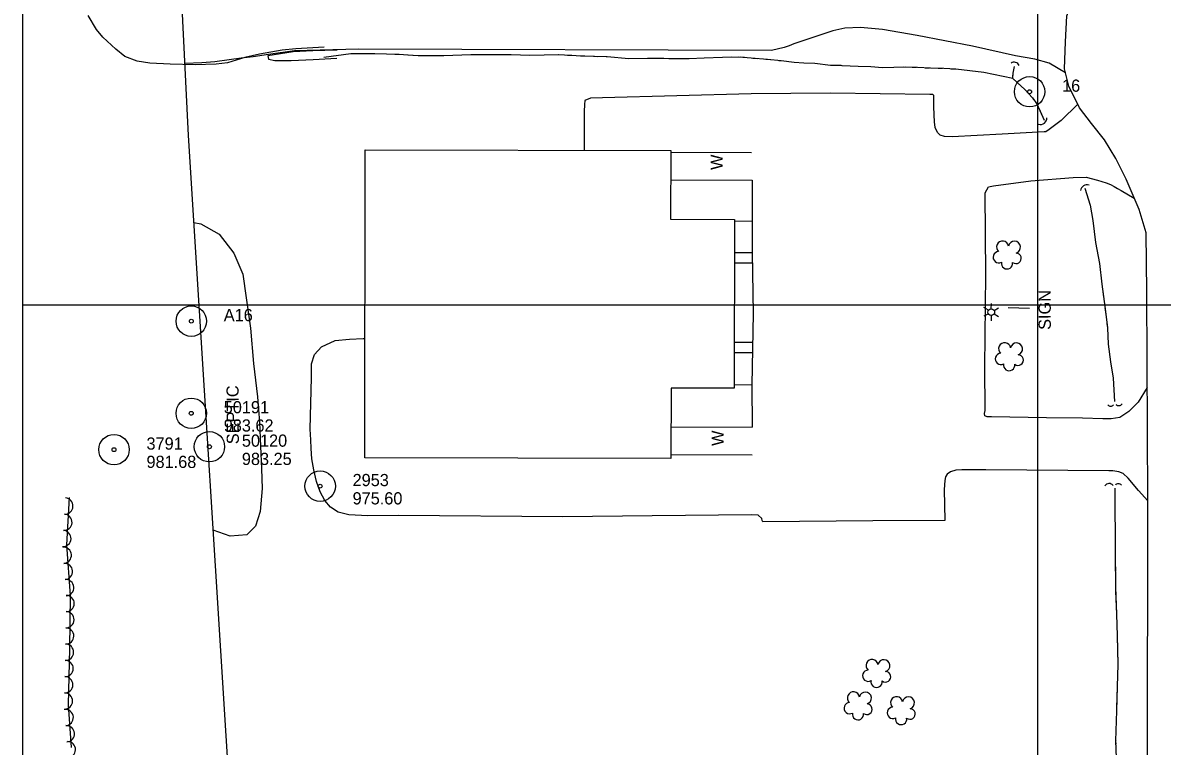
# Model space of a CAD drawing. Extents: x 353423 to 364002, y 127000 to 201942.
# Drawn here: x 360000 to 360561, y 134283 to 134639 of the extents above; entities that cross this region are included whole.
import ezdxf

# ---------------------------------------------------------------- set-up
doc = ezdxf.new("R2010")
doc.units = 0
for name, color, linetype in [('E_DTM_SlopeBottom', 7, 'Continuous'), ('E_DTM_SlopeTop', 7, 'Continuous'), ('E_FEN_Generic', 7, 'Continuous'), ('E_LAND_BrushLine', 7, 'Continuous'), ('E_LAND_TreeLine', 7, 'Continuous'), ('E_MISCPROP', 7, 'Continuous'), ('E_RDWY_AsphConc', 7, 'Continuous'), ('E_RDWY_Gravel', 7, 'Continuous'), ('E_STRUCT_WingWall', 7, 'Continuous'), ('E_UTL_ETransformer', 7, 'Continuous'), ('E_WTR_FlowLine', 7, 'Continuous')]:
    doc.layers.add(name, color=color, linetype=linetype)

msp = doc.modelspace()

# ---------------------------------------------------------------- linework, layer by layer
at = {"layer": 'E_DTM_SlopeBottom'}
for points in [[(360319.17, 134575.09), (360358.92, 134574.91)], [(360319.15, 134561.46), (360359.28, 134561.35)], [(360319.27, 134439.83), (360359.23, 134439.78)], [(360319.25, 134426.18), (360359.19, 134426.11)]]:
    msp.add_lwpolyline(points, dxfattribs=at)
for centre, radius, start, end in [((360488.37, 134616.83), 2.57, 22.214, 128.4535), ((360501.19, 134591.99), 3.26, 254.8922, 1.1318), ((360524.12, 134555.93), 3.07, 69.1026, 175.3422), ((360539.85, 134452.26), 1.96, 222.417, 328.6565), ((360535.83, 134451.76), 1.72, 217.3993, 323.6389), ((360535.08, 134409.43), 2.52, 38.8099, 145.0494), ((360539.67, 134410.02), 1.86, 38.2653, 144.5049)]:
    msp.add_arc(centre, radius, start, end, dxfattribs=at)
at = {"layer": 'E_DTM_SlopeTop'}
msp.add_lwpolyline([(360554.05, 134269.46), (360554.09, 134403.92), (360553.63, 134506.29), (360553.37, 134535.42), (360549.86, 134546.8), (360543.54, 134561.85), (360538.34, 134571.93), (360532.81, 134581.11), (360526.34, 134589.2), (360520.57, 134596.9), (360515.23, 134607.66), (360513.1, 134616.09), (360513.61, 134629.43), (360514.27, 134642.21), (360517.01, 134649.05), (360520.34, 134654.93), (360525, 134659.58), (360529.55, 134664.15), (360535.92, 134669.8), (360542.83, 134674.49), (360548.9, 134677.17), (360554.53, 134678.74), (360561.11, 134679.89), (360568.24, 134680.29)], dxfattribs=at)
at = {"layer": 'E_FEN_Generic'}
msp.add_lwpolyline([(360024.07, 134281.98), (360022.56, 134302.95), (360023.16, 134330.76), (360023.5, 134356.82), (360021.67, 134381.8), (360023.09, 134405.02)], dxfattribs=at)
for centre, radius, start, end in [((360482.6, 134528.4), 2.97, 8.4104, 229.6443), ((360488.45, 134528.29), 2.97, 286.0613, 169.0345), ((360480.74, 134523.36), 2.78, 91.3813, 299.1543), ((360489.22, 134522.82), 2.61, 230.7665, 88.6991), ((360484.82, 134520.36), 2.78, 168.0584, 9.0694), ((360483.63, 134478.32), 2.97, 8.4104, 229.6443), ((360489.48, 134478.21), 2.97, 286.0613, 169.0345), ((360481.77, 134473.28), 2.78, 91.3813, 299.1543), ((360490.24, 134472.74), 2.61, 230.7665, 88.6991), ((360485.84, 134470.28), 2.78, 168.0584, 9.0694), ((360020.74, 134400.88), 4, 266.5093, 86.4939), ((360020.25, 134392.89), 4, 266.5093, 86.4939), ((360019.76, 134384.91), 4, 266.5093, 86.4939), ((360019.95, 134376.65), 4, 274.2019, 94.1866), ((360020.53, 134368.67), 4, 274.2019, 94.1866), ((360021.12, 134360.69), 4, 274.2019, 94.1866), ((360021.36, 134352.89), 4, 269.2523, 89.237), ((360021.25, 134344.89), 4, 269.2523, 89.237), ((360021.15, 134336.89), 4, 269.2523, 89.237), ((360021.03, 134328.91), 4, 268.771, 88.7557), ((360020.85, 134320.91), 4, 268.771, 88.7557), ((360418.31, 134322.38), 2.97, 8.4104, 229.6443), ((360424.17, 134322.27), 2.97, 286.0613, 169.0345), ((360020.68, 134312.92), 4, 268.771, 88.7557), ((360416.45, 134317.34), 2.78, 91.3813, 299.1543), ((360424.93, 134316.8), 2.61, 230.7665, 88.6991), ((360420.53, 134314.34), 2.78, 168.0584, 9.0694), ((360020.51, 134304.92), 4, 268.771, 88.7557), ((360409.16, 134306.42), 2.97, 8.4104, 229.6443), ((360415.02, 134306.31), 2.97, 286.0613, 169.0345), ((360430.4, 134304.07), 2.97, 8.4104, 229.6443), ((360436.25, 134303.96), 2.97, 286.0613, 169.0345), ((360020.91, 134296.74), 4, 274.1321, 94.1168), ((360407.3, 134301.38), 2.78, 91.3813, 299.1543), ((360415.78, 134300.84), 2.61, 230.7665, 88.6991), ((360428.54, 134299.03), 2.78, 91.3813, 299.1543), ((360437.02, 134298.49), 2.61, 230.7665, 88.6991), ((360411.38, 134298.38), 2.78, 168.0584, 9.0694), ((360432.62, 134296.03), 2.78, 168.0584, 9.0694), ((360021.48, 134288.76), 4, 274.1321, 94.1168), ((360021.96, 134280.97), 4, 268.8197, 88.8044)]:
    msp.add_arc(centre, radius, start, end, dxfattribs=at)
at = {"layer": 'E_LAND_BrushLine'}
for p, q in [((360475.61, 134497.27), (360473.37, 134498.62)), ((360477.05, 134498.01), (360477.11, 134500.53)), ((360478.51, 134497.14), (360480.67, 134498.39)), ((360495.9, 134498.11), (360485.41, 134498.4)), ((360475.61, 134495.56), (360473.32, 134494.35)), ((360476.98, 134494.74), (360476.92, 134492.13)), ((360478.47, 134495.5), (360480.67, 134494.15))]:
    msp.add_line(p, q, dxfattribs=at)
msp.add_circle((360477.04, 134496.37), 1.64, dxfattribs=at)
at = {"layer": 'E_LAND_TreeLine'}
for p, q in [((360000, 134500), (360000, 136500)), ((360500, 134500), (360500, 136500)), ((360000, 132500), (360000, 135000)), ((360500, 132500), (360500, 135000)), ((360000, 134500), (364000, 134500)), ((360000, 134500), (364000, 134500))]:
    msp.add_line(p, q, dxfattribs=at)
at = {"layer": 'E_MISCPROP'}
for points in [[(360148.41, 134626.81), (360134.44, 134625.99), (360127.68, 134625.25), (360116.54, 134623.26), (360109.34, 134621.65), (360100.86, 134619.07), (360095.17, 134618.39), (360084.94, 134618.13), (360072.65, 134618.35), (360062.64, 134618.9), (360056.3, 134619.84), (360050.22, 134622.25), (360045.88, 134625.81), (360039.35, 134631.73), (360036.36, 134635.51), (360032.27, 134642.31)], [(360513.58, 134614.18), (360505.53, 134618.94), (360498.48, 134620.86), (360488.94, 134622.5), (360467.79, 134627.31), (360440.5, 134632.46), (360423.4, 134635.46), (360412.7, 134636.52), (360404.92, 134636.15), (360398.94, 134634.85), (360387.69, 134631.08), (360379.87, 134628.39), (360377.51, 134627.37), (360374.95, 134626.6), (360368.85, 134625.21), (360165.32, 134625.86), (360133.82, 134625.03), (360121.02, 134623.14), (360113.42, 134622.07), (360107.54, 134621.36), (360101.62, 134620.53), (360094.63, 134619.51), (360088.13, 134619.06), (360079.88, 134618.7)], [(360154.87, 134625.38), (360142.8, 134625.05), (360133.11, 134624.41), (360120.73, 134622.46), (360121, 134620.95), (360124.09, 134620.2), (360132.16, 134620.3), (360143.09, 134620.72), (360154.77, 134621.29)], [(360519.69, 134598.67), (360511.53, 134590.7), (360505.5, 134586.25), (360503.92, 134585.12), (360503.03, 134585.07), (360482.45, 134583.98), (360457.84, 134582.59), (360454.03, 134582.84), (360451.9, 134583.46), (360450.58, 134584.72), (360449.37, 134587.18), (360449.04, 134590.05), (360448.9, 134593.53), (360448.76, 134597.64), (360448.77, 134602.95), (360448.3, 134603.5), (360446.79, 134603.53), (360397.79, 134604.19), (360358.82, 134603.79), (360285.59, 134601.92), (360279.66, 134601.68), (360276.92, 134600.54), (360276.71, 134598.55), (360276.52, 134595.16), (360276.58, 134576.01)], [(360359.28, 134561.35), (360359.28, 134525.75), (360359.76, 134495.72), (360359.16, 134460.58), (360359.23, 134439.78)], [(360553.84, 134459.31), (360549.44, 134452.02), (360544.76, 134447.35), (360540.32, 134444.45), (360536.14, 134443.82), (360531.95, 134443.88), (360522.01, 134444.07), (360504.22, 134444.3), (360477.2, 134444.74), (360475.06, 134444.76), (360473.88, 134445.32), (360473.78, 134446.46), (360473.99, 134447.97), (360473.91, 134469.49), (360474.3, 134514.78), (360474.04, 134555.04), (360475.65, 134558.05), (360476.48, 134558.22), (360478.14, 134558.53), (360496.45, 134561.06), (360517.33, 134562.63), (360523.82, 134562.72), (360529.35, 134561.34), (360533.7, 134559.98), (360535.85, 134559.12), (360537.61, 134558.15), (360539.29, 134557.22), (360540.99, 134556.14), (360547.49, 134552.45)], [(360359.28, 134541), (360350.49, 134541.12)], [(360359.28, 134525.48), (360350.47, 134525.47)], [(360359.36, 134520.47), (360350.46, 134520.46)], [(360554.09, 134403.39), (360549.59, 134408.5), (360544.5, 134414.65), (360541.98, 134416.89), (360539.81, 134417.68), (360536.85, 134418.14), (360534.91, 134418.16), (360474.3, 134418.66), (360462.62, 134418.68), (360459.58, 134418.53), (360456.97, 134417.64), (360455.34, 134416.58), (360454.52, 134415.3), (360454.14, 134413.38), (360453.92, 134408.94), (360454.2, 134393.76), (360418.71, 134393.6), (360364.57, 134393.12), (360364.24, 134393.78), (360363.98, 134394.66), (360362.18, 134396.3), (360359.06, 134396.5), (360310.09, 134396.02), (360266.02, 134395.6), (360185.14, 134396.22), (360169.94, 134396.01), (360160.55, 134396.6), (360155.39, 134397.94), (360151.53, 134400.29), (360148.7, 134403.63), (360146.43, 134407.93), (360144.71, 134412.99), (360143.38, 134418.67), (360142.44, 134424.16), (360142.06, 134429.15), (360141.88, 134433.39), (360141.52, 134438.7), (360142.23, 134464.22), (360142.15, 134470.87), (360143.63, 134475.47), (360147.12, 134479.27), (360153.87, 134482.39), (360160.96, 134483.03), (360167.69, 134483.34), (360168.55, 134483.34)], [(360359.52, 134481.41), (360350.39, 134481.32)], [(360359.43, 134476.29), (360350.39, 134476.27)], [(360359.16, 134460.42), (360350.36, 134460.61)]]:
    msp.add_lwpolyline(points, dxfattribs=at)
at = {"layer": 'E_RDWY_AsphConc'}
for centre, radius in [((360495.93, 134604.85), 7.5), ((360495.93, 134604.85), 7.5), ((360495.93, 134604.85), 0.96), ((360495.93, 134604.85), 0.96), ((360083, 134491.89), 7.5), ((360083, 134491.89), 7.5), ((360083, 134491.89), 0.96), ((360083, 134491.89), 0.96), ((360082.98, 134446.54), 7.5), ((360082.98, 134446.54), 7.5), ((360082.98, 134446.54), 0.96), ((360082.98, 134446.54), 0.96), ((360044.93, 134428.63), 7.5), ((360044.93, 134428.63), 7.5), ((360091.92, 134430.08), 7.5), ((360091.92, 134430.08), 7.5), ((360044.93, 134428.63), 0.96), ((360044.93, 134428.63), 0.96), ((360091.92, 134430.08), 0.96), ((360091.92, 134430.08), 0.96), ((360146.45, 134410.67), 7.5), ((360146.45, 134410.67), 7.5), ((360146.45, 134410.67), 0.96), ((360146.45, 134410.67), 0.96)]:
    msp.add_circle(centre, radius, dxfattribs=at)
at = {"layer": 'E_RDWY_Gravel'}
for points in [[(360081.63, 134583.34), (360055.9, 135105.05), (360854.06, 136259.02)], [(360226.78, 132878.09), (360145.09, 133571.05), (360081.63, 134583.34)]]:
    msp.add_lwpolyline(points, dxfattribs=at)
at = {"layer": 'E_STRUCT_WingWall'}
for points in [[(360487.62, 134611.38), (360473.31, 134614.3), (360466.43, 134615.1), (360459.54, 134615.89), (360453.61, 134616.23), (360447.18, 134616.4), (360440.66, 134616.71), (360434.88, 134616.89), (360428.98, 134616.77), (360423.5, 134616.63), (360417.7, 134617.05), (360411.47, 134617.33), (360403.53, 134617.67), (360397.83, 134617.82), (360390.13, 134618.69), (360384.69, 134618.96), (360379.93, 134619.24), (360373.62, 134620.01), (360366.81, 134620.69), (360358.84, 134621.33), (360352.68, 134621.9), (360344.67, 134621.7), (360335.7, 134621.42), (360328.25, 134621.09), (360321.38, 134621.09), (360315.73, 134621.13), (360310.56, 134621.24), (360307.69, 134621.24), (360298.55, 134620.99), (360287.77, 134621.96), (360275.49, 134622.32), (360263.88, 134623.03), (360249.82, 134622.7), (360240.57, 134623), (360230.11, 134622.94), (360220.68, 134622.97), (360207.46, 134622.53), (360194.72, 134622.54), (360185.02, 134623.19), (360173.47, 134623.55), (360161.52, 134623.58), (360148.31, 134621.62)], [(360179.01, 134623.38), (360173.47, 134623.55), (360161.52, 134623.58), (360148.31, 134621.62)], [(360185.39, 134623.17), (360185.02, 134623.19), (360183.27, 134623.24)], [(360191.76, 134622.74), (360189.64, 134622.88)], [(360198.13, 134622.54), (360196.01, 134622.54)], [(360233.23, 134622.96), (360230.11, 134622.94), (360220.68, 134622.97), (360207.46, 134622.53), (360202.39, 134622.54)], [(360264.06, 134623.02), (360263.88, 134623.03), (360249.82, 134622.7), (360240.57, 134623), (360233.23, 134622.96)], [(360270.43, 134622.63), (360268.31, 134622.76)], [(360276.8, 134622.28), (360275.49, 134622.32), (360274.68, 134622.37)], [(360283.18, 134622.09), (360281.05, 134622.16)], [(360318.22, 134621.11), (360315.73, 134621.13), (360310.56, 134621.24), (360307.69, 134621.24), (360298.55, 134620.99), (360287.77, 134621.96), (360287.43, 134621.97)], [(360349.05, 134621.81), (360344.67, 134621.7), (360335.7, 134621.42), (360328.25, 134621.09), (360321.38, 134621.09), (360318.22, 134621.11)], [(360355.42, 134621.64), (360353.3, 134621.84)], [(360361.77, 134621.1), (360359.65, 134621.26)], [(360368.13, 134620.56), (360366.81, 134620.69), (360366.01, 134620.76)], [(360403.07, 134617.69), (360397.83, 134617.82), (360390.13, 134618.69), (360384.69, 134618.96), (360379.93, 134619.24), (360373.62, 134620.01), (360372.36, 134620.13)], [(360433.83, 134616.87), (360428.98, 134616.77), (360423.5, 134616.63), (360417.7, 134617.05), (360411.47, 134617.33), (360403.53, 134617.67), (360403.07, 134617.69)], [(360440.19, 134616.73), (360438.07, 134616.79)], [(360446.57, 134616.43), (360444.44, 134616.53)], [(360452.94, 134616.25), (360450.82, 134616.3)], [(360487.62, 134611.38), (360473.31, 134614.3), (360466.43, 134615.1), (360459.54, 134615.89), (360457.19, 134616.03)], [(360493.63, 134605.99), (360487.62, 134611.38), (360487.88, 134614.02), (360488.44, 134617.33)], [(360487.7, 134612.26), (360487.88, 134614.02), (360488.44, 134617.33)], [(360487.75, 134611.26), (360487.62, 134611.38), (360487.63, 134611.55)], [(360488.53, 134610.56), (360488.27, 134610.79)], [(360489.32, 134609.86), (360489.06, 134610.09)], [(360493.63, 134605.99), (360489.84, 134609.39)], [(360493.63, 134605.99), (360497.36, 134601.84), (360499.46, 134598.9), (360503.1, 134590.83)], [(360493.63, 134605.99), (360497.36, 134601.84), (360497.92, 134601.06)], [(360498.45, 134600.32), (360498.71, 134599.96)], [(360499.23, 134599.22), (360499.46, 134598.9), (360499.48, 134598.85)], [(360499.85, 134598.03), (360500.04, 134597.62)], [(360500.41, 134596.79), (360503.1, 134590.83)], [(360523.2, 134557.31), (360525.78, 134549.06), (360527.06, 134541.43), (360528.45, 134530.69), (360530.33, 134520.21), (360531.44, 134510.11), (360533.13, 134497.91), (360534.24, 134488.69), (360534.64, 134480.57), (360535.76, 134471.86), (360537.14, 134463.88), (360537.71, 134452.38)], [(360523.2, 134557.31), (360525.78, 134549.06), (360527.06, 134541.43), (360528.45, 134530.69), (360530.33, 134520.21), (360530.4, 134519.59)], [(360530.98, 134514.31), (360531.27, 134511.67)], [(360531.95, 134506.4), (360532.32, 134503.77)], [(360533.05, 134498.51), (360533.13, 134497.91), (360533.38, 134495.89)], [(360534, 134490.63), (360534.24, 134488.69), (360534.64, 134480.57), (360535.76, 134471.86), (360537.14, 134463.88), (360537.71, 134452.38)], [(360537.96, 134409.65), (360537.9, 134398.35), (360537.99, 134387.61), (360538.11, 134376.59), (360538.24, 134360.88), (360538.75, 134347.63), (360539.02, 134336.95), (360539.4, 134322.87), (360539.01, 134311.98), (360538.65, 134300.03), (360538.31, 134285.27), (360538.7, 134272.68)], [(360537.96, 134409.65), (360537.9, 134398.35), (360537.99, 134387.61), (360538.06, 134380.86)], [(360538.1, 134376.89), (360538.11, 134376.59), (360538.12, 134374.9)], [(360538.16, 134370.93), (360538.17, 134368.94)], [(360538.21, 134364.97), (360538.22, 134362.98)], [(360538.31, 134359.01), (360538.75, 134347.63), (360539.02, 134336.95), (360539.2, 134330.23)], [(360539.2, 134330.23), (360539.4, 134322.87), (360539.01, 134311.98), (360538.69, 134301.44)], [(360538.59, 134297.47), (360538.55, 134295.49)], [(360538.46, 134291.52), (360538.41, 134289.53)], [(360538.32, 134285.56), (360538.31, 134285.27), (360538.37, 134283.58)]]:
    msp.add_lwpolyline(points, dxfattribs=at)
at = {"layer": 'E_UTL_ETransformer'}
msp.add_lwpolyline([(360084.32, 134540.39), (360087.7, 134539.83), (360096.76, 134534.73), (360103.99, 134525.41), (360108.33, 134515), (360109.98, 134503.32), (360112.17, 134488.43), (360113.62, 134471.1), (360115.66, 134454.63), (360116.55, 134442.12), (360117.15, 134430.28), (360117.63, 134419.13), (360117.99, 134409.45), (360116.85, 134398.15), (360114.65, 134390.89), (360110.4, 134386.78), (360102.22, 134385.98), (360093.81, 134388.94)], dxfattribs=at)
at = {"layer": 'E_WTR_FlowLine'}
msp.add_lwpolyline([(360168.45, 134424.61), (360168.7, 134576.18), (360319.17, 134575.94), (360319.12, 134542.07), (360350.49, 134542.02), (360350.36, 134458.88), (360319.3, 134458.93), (360319.24, 134424.36)], close=True, dxfattribs=at)

# ---------------------------------------------------------------- texts
at = {"layer": 'E_DTM_SlopeBottom'}
for p in [(360344.78, 134566.37), (360345.29, 134430.5)]:
    msp.add_text('W', height=6, rotation=90.1973, dxfattribs=at).set_placement(p)
at = {"layer": 'E_LAND_BrushLine'}
msp.add_text('SIGN', height=6, rotation=90.2558, dxfattribs=at).set_placement((360506.39, 134487.61))
at = {"layer": 'E_RDWY_AsphConc'}
for s, p in [('16', (360511.93, 134604.85)), ('16', (360511.93, 134604.85)), ('A16', (360099, 134491.89)), ('A16', (360099, 134491.89)), ('50191', (360098.98, 134446.54)), ('50191', (360098.98, 134446.54)), ('983.62', (360098.98, 134437.54)), ('983.62', (360098.98, 134437.54)), ('3791', (360060.93, 134428.63)), ('3791', (360060.93, 134428.63)), ('50120', (360107.92, 134430.08)), ('50120', (360107.92, 134430.08)), ('981.68', (360060.93, 134419.63)), ('981.68', (360060.93, 134419.63)), ('983.25', (360107.92, 134421.08)), ('983.25', (360107.92, 134421.08)), ('2953', (360162.45, 134410.67)), ('2953', (360162.45, 134410.67)), ('975.60', (360162.45, 134401.67)), ('975.60', (360162.45, 134401.67))]:
    msp.add_text(s, height=6, dxfattribs=at).set_placement(p)
at = {"layer": 'E_UTL_ETransformer'}
msp.add_text('SEPTIC', height=6, rotation=90.2558, dxfattribs=at).set_placement((360106.45, 134431.31))

doc.saveas('drawing.dxf')
